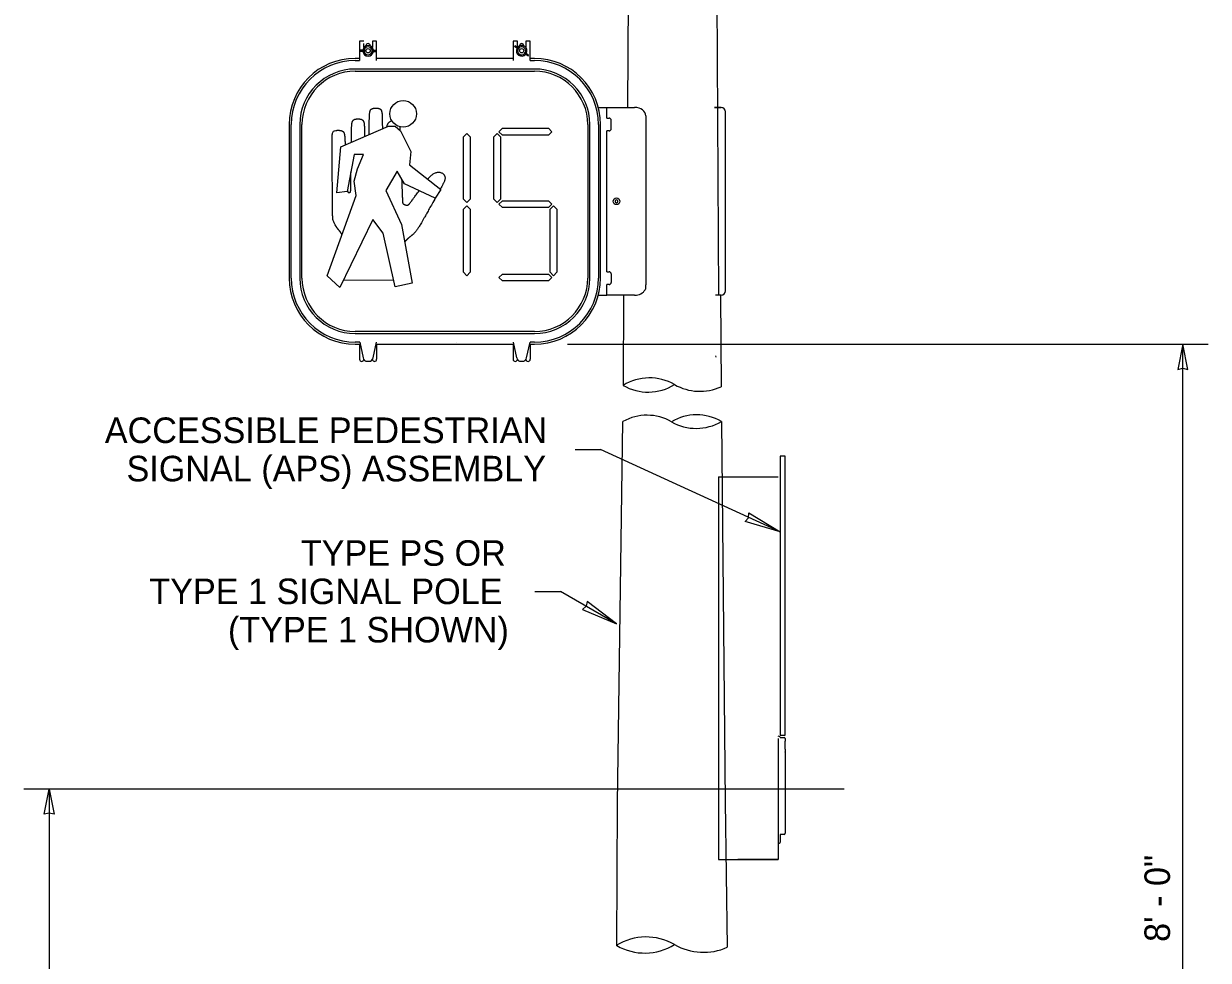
# Model space of a CAD drawing. Extents: x 99862 to 103680, y 99470 to 105076.
# Drawn here: x 101008 to 101750, y 103974 to 104561 of the extents above; entities that cross this region are included whole.
import ezdxf

# ---------------------------------------------------------------- set-up
doc = ezdxf.new("R2010")
doc.units = 0
for name, color, linetype in [('Level 1', 7, 'Continuous'), ('Level 11', 7, 'Continuous'), ('Level 15', 7, 'Continuous'), ('Level 2', 7, 'Continuous'), ('Level 20', 7, 'Continuous'), ('Level 3', 7, 'Continuous'), ('Level 31', 7, 'Continuous'), ('Level 33', 7, 'Continuous'), ('Level 4', 7, 'Continuous'), ('Level 40', 7, 'Continuous'), ('Level 5', 7, 'Continuous'), ('Level 6', 7, 'Continuous'), ('Level 7', 7, 'Continuous'), ('Level 8', 7, 'Continuous')]:
    doc.layers.add(name, color=color, linetype=linetype)

msp = doc.modelspace()

# ---------------------------------------------------------------- linework, layer by layer
at = {"layer": 'Level 1'}
for p, q in [((101218.5, 104359.78), (101218.5, 104353.11)), ((101229.19, 104359.78), (101229.19, 104353.11)), ((101314.69, 104359.78), (101314.69, 104353.11)), ((101325.38, 104359.78), (101325.38, 104353.11)), ((101218.5, 104353.11), (101218.5, 104350.43)), ((101229.19, 104353.11), (101229.19, 104350.43)), ((101314.69, 104353.11), (101314.69, 104350.43)), ((101325.38, 104353.11), (101325.38, 104350.43)), ((101441.95, 104351.66), (101441.62, 104352.51))]:
    msp.add_line(p, q, dxfattribs=at)
for centre, start, end in [((101219.84, 104350.43), 180, 270), ((101219.84, 104350.43), 270, 350.91675), ((101227.86, 104350.43), 189.08325, 270), ((101227.86, 104350.43), 270, 0), ((101316.03, 104350.43), 180, 270), ((101316.03, 104350.43), 270, 350.91675), ((101324.04, 104350.43), 189.08325, 270), ((101324.04, 104350.43), 270, 0)]:
    msp.add_arc(centre, 1.34, start, end, dxfattribs=at)
at = {"layer": 'Level 11'}
msp.add_line((101279.06, 104361.02), (101279.09, 104361.12), dxfattribs=at)
at = {"layer": 'Level 15'}
for p, q in [((101348.74, 104359.78), (101750.13, 104359.78)), ((101734.13, 103694.63), (101734.13, 104359.78)), ((101353.51, 104293.95), (101369.51, 104293.95)), ((101482.04, 104242.25), (101369.51, 104293.95)), ((101328.28, 104205.08), (101344.28, 104205.08)), ((101379.4, 104184.81), (101344.28, 104205.08)), ((101522.08, 104081.21), (101008.13, 104081.21)), ((101024.13, 104081.21), (101024.13, 103694.63))]:
    msp.add_line(p, q, dxfattribs=at)
for points in [[(101734.13, 104359.78), (101731.05, 104344.06), (101734.13, 104344.79), (101737.22, 104344.06)], [(101482.04, 104242.25), (101459.99, 104248.89), (101462.18, 104251.18), (101462.44, 104254.33)], [(101379.4, 104184.81), (101361.12, 104198.81), (101360.54, 104195.7), (101358.13, 104193.64)], [(101024.13, 104081.21), (101027.22, 104065.49), (101024.13, 104066.22), (101021.05, 104065.49)]]:
    msp.add_lwpolyline(points, close=True, dxfattribs=at)
at = {"layer": 'Level 2'}
for p, q in [((101239.95, 104399.78), (101208.3, 104399.89)), ((101251.41, 104398.14), (101240.89, 104395.66))]:
    msp.add_line(p, q, dxfattribs=at)
for points in [[(101240.89, 104395.66), (101233.21, 104429.27), (101226.78, 104437.89), (101206.1, 104395.39), (101198.22, 104402.58), (101216.4, 104452.88), (101215.07, 104461.97), (101217.2, 104469.73), (101220.97, 104478.69), (101215.07, 104478.6), (101210.77, 104455.36), (101204.29, 104454.61), (101206.68, 104483.31), (101236.72, 104496.26), (101240.8, 104496.26), (101244.08, 104493.51), (101250.64, 104480.42), (101249.71, 104472.13), (101269.37, 104456.65), (101265.85, 104451.33), (101246.7, 104460.15), (101241.99, 104468.19), (101234.99, 104456.02), (101244.75, 104434.73), (101251.41, 104398.14)], [(101287.72, 104450.74), (101285.62, 104448.63), (101285.62, 104448.63), (101283.51, 104450.74), (101283.51, 104450.74), (101283.51, 104489.73), (101283.51, 104489.73), (101285.62, 104491.84), (101285.62, 104491.84), (101287.72, 104489.73), (101287.72, 104489.73), (101287.72, 104450.74)], [(101306.88, 104450.74), (101304.77, 104448.63), (101304.77, 104448.63), (101302.66, 104450.74), (101302.66, 104450.74), (101302.66, 104489.73), (101302.66, 104489.73), (101304.77, 104491.84), (101304.77, 104491.84), (101306.88, 104489.73), (101306.88, 104489.73), (101306.88, 104450.74)], [(101336.89, 104495.01), (101339, 104492.9), (101339, 104492.9), (101336.89, 104490.79), (101336.89, 104490.79), (101307.94, 104490.79), (101307.94, 104490.79), (101305.83, 104492.9), (101305.83, 104492.9), (101307.94, 104495.01), (101307.94, 104495.01), (101336.89, 104495.01)], [(101287.72, 104404.83), (101285.62, 104402.72), (101285.62, 104402.72), (101283.51, 104404.83), (101283.51, 104404.83), (101283.51, 104444.41), (101283.51, 104444.41), (101285.62, 104446.52), (101285.62, 104446.52), (101287.72, 104444.41), (101287.72, 104444.41), (101287.72, 104404.83)], [(101336.89, 104449.68), (101339, 104447.57), (101339, 104447.57), (101336.89, 104445.46), (101336.89, 104445.46), (101307.94, 104445.46), (101307.94, 104445.46), (101305.83, 104447.57), (101305.83, 104447.57), (101307.94, 104449.68), (101307.94, 104449.68), (101336.89, 104449.68)], [(101342.17, 104404.83), (101340.06, 104402.72), (101340.06, 104402.72), (101337.95, 104404.83), (101337.95, 104404.83), (101337.95, 104444.41), (101337.95, 104444.41), (101340.06, 104446.52), (101340.06, 104446.52), (101342.17, 104444.41), (101342.17, 104444.41), (101342.17, 104404.83)], [(101336.89, 104403.77), (101339, 104401.66), (101339, 104401.66), (101336.89, 104399.55), (101336.89, 104399.55), (101307.94, 104399.55), (101307.94, 104399.55), (101305.83, 104401.66), (101305.83, 104401.66), (101307.94, 104403.77), (101307.94, 104403.77), (101336.89, 104403.77)]]:
    msp.add_lwpolyline(points, dxfattribs=at)
msp.add_circle((101245.83, 104504.07), 8.35, dxfattribs=at)
for points in [[(101224.47, 104490.98), (101224.57, 104497.33), (101224.68, 104503.68), (101224.68, 104507.69), (101228.69, 104507.69), (101232.7, 104507.69), (101232.7, 104503.68), (101232.75, 104499.12), (101232.8, 104494.57)], [(101213.39, 104486.2), (101213.46, 104491.55), (101213.53, 104496.91), (101213.53, 104500.92), (101217.53, 104500.92), (101221.54, 104500.92), (101221.54, 104496.91), (101221.57, 104493.32), (101221.6, 104489.74)], [(101235.65, 104495.8), (101235.65, 104495.8), (101235.65, 104495.81), (101235.65, 104498.96), (101238.71, 104499.7)], [(101207.54, 104428.36), (101206.72, 104429.88), (101205.59, 104431.2), (101204, 104433.05), (101202.87, 104435.2), (101201.64, 104437.54), (101201.64, 104440.18), (101201.43, 104464.97), (101201.22, 104489.77), (101201.22, 104493.78), (101205.23, 104493.78), (101209.24, 104493.78), (101209.24, 104489.77), (101209.37, 104487.15), (101209.51, 104484.53)], [(101243.66, 104496), (101243.67, 104495.9), (101243.67, 104495.81), (101243.7, 104494.8), (101243.74, 104493.8)], [(101210.97, 104456.42), (101210.98, 104456.12), (101211, 104455.83), (101211, 104454.83), (101212, 104454.83), (101213, 104454.83), (101213, 104455.83), (101213.08, 104462.05), (101213.16, 104468.27)], [(101261.24, 104463.05), (101261.34, 104463.18), (101261.44, 104463.32), (101266.56, 104470.83), (101274.07, 104465.7), (101271.58, 104461.28), (101269.09, 104456.86)], [(101244.88, 104463.26), (101245.14, 104456.28), (101245.4, 104449.31), (101245.4, 104449.39), (101245.39, 104449.47), (101245.4, 104447.6), (101247.2, 104447.07), (101248.99, 104446.55), (101250.01, 104448.12), (101249.9, 104447.98), (101249.79, 104447.83), (101252.83, 104451.88), (101255.88, 104455.92)], [(101266.7, 104452.61), (101261.39, 104443.16), (101256.07, 104433.72), (101253.77, 104429.64), (101249.98, 104426.89), (101248.14, 104425.56), (101246.74, 104423.77)]]:
    msp.add_open_spline(points, degree=4, dxfattribs=at)
at = {"layer": 'Level 3'}
for p, q in [((101221.18, 104549.49), (101218.5, 104549.49)), ((101218.5, 104549.49), (101218.5, 104537.46)), ((101221.18, 104545.54), (101221.18, 104548.15)), ((101226.51, 104549.49), (101226.52, 104545.55)), ((101229.19, 104549.49), (101226.52, 104549.49)), ((101229.19, 104537.46), (101229.19, 104549.49)), ((101317.36, 104549.49), (101314.69, 104549.49)), ((101314.69, 104549.49), (101314.69, 104537.46)), ((101317.36, 104548.15), (101317.36, 104549.49)), ((101317.36, 104545.79), (101317.36, 104548.15)), ((101322.7, 104549.49), (101322.71, 104545.55)), ((101325.38, 104549.49), (101322.71, 104549.49)), ((101325.38, 104537.46), (101325.38, 104549.49)), ((101218.5, 104538.8), (101215.83, 104538.8)), ((101215.83, 104537.46), (101218.5, 104537.46)), ((101314.69, 104538.8), (101229.19, 104538.8)), ((101328.05, 104538.8), (101325.38, 104538.8)), ((101325.38, 104537.46), (101328.05, 104537.46)), ((101328.05, 104532.12), (101215.83, 104532.12)), ((101215.83, 104530.78), (101328.05, 104530.78)), ((101174.42, 104497.39), (101174.42, 104401.2)), ((101175.75, 104401.2), (101175.75, 104497.39)), ((101181.1, 104497.39), (101181.1, 104401.2)), ((101182.43, 104401.2), (101182.43, 104497.39)), ((101361.45, 104497.39), (101361.45, 104401.2)), ((101362.79, 104401.2), (101362.79, 104497.39)), ((101368.13, 104497.39), (101368.13, 104401.2)), ((101369.47, 104401.2), (101369.47, 104497.39)), ((101328.05, 104367.8), (101215.83, 104367.8)), ((101215.83, 104366.46), (101328.05, 104366.46)), ((101218.61, 104361.12), (101215.83, 104361.12)), ((101215.83, 104359.78), (101218.9, 104359.78)), ((101218.61, 104361.12), (101220.73, 104351.21)), ((101226.97, 104351.21), (101229.09, 104361.12)), ((101228.8, 104359.78), (101315.08, 104359.78)), ((101314.8, 104361.12), (101316.91, 104351.21)), ((101323.16, 104351.21), (101325.27, 104361.12)), ((101324.99, 104359.78), (101328.05, 104359.78)), ((101328.05, 104361.12), (101325.27, 104361.12)), ((101223.34, 104349.1), (101224.36, 104349.1)), ((101319.53, 104349.1), (101320.55, 104349.1))]:
    msp.add_line(p, q, dxfattribs=at)
for centre, radius, start, end in [((101215.83, 104497.39), 41.41, 90, 180), ((101215.83, 104497.39), 40.08, 90, 180), ((101328.05, 104497.39), 41.41, 0, 90), ((101328.05, 104497.39), 40.08, 0, 90), ((101215.83, 104497.39), 34.73, 90, 180), ((101215.83, 104497.39), 33.4, 90, 180), ((101328.05, 104497.39), 34.73, 0, 90), ((101328.05, 104497.39), 33.4, 0, 90), ((101215.83, 104401.2), 41.41, 180, 270), ((101215.83, 104401.2), 40.08, 180, 270), ((101215.83, 104401.2), 34.73, 180, 270), ((101215.83, 104401.2), 33.4, 180, 270), ((101328.05, 104401.2), 41.41, 270, 0), ((101328.05, 104401.2), 34.73, 270, 0), ((101328.05, 104401.2), 40.08, 270, 0), ((101328.05, 104401.2), 33.4, 270, 0), ((101223.34, 104351.77), 2.67, 192.04709, 270), ((101224.36, 104351.77), 2.67, 270, 347.95291), ((101319.53, 104351.77), 2.67, 192.04709, 270), ((101320.55, 104351.77), 2.67, 270, 347.95291)]:
    msp.add_arc(centre, radius, start, end, dxfattribs=at)
at = {"layer": 'Level 31'}
for p, q in [((101443.29, 104276.7), (101480.69, 104276.7)), ((101443.29, 104276.7), (101443.29, 104037.17)), ((101480.69, 104112.91), (101480.69, 104047.68)), ((101480.69, 104047.68), (101480.69, 104037.17)), ((101443.29, 104037.17), (101480.69, 104037.17))]:
    msp.add_line(p, q, dxfattribs=at)
at = {"layer": 'Level 33'}
for p, q in [((101481.86, 104113.61), (101484.37, 104113.61)), ((101485.07, 104106.3), (101485.08, 104111.18)), ((101485.08, 104112.91), (101485.08, 104111.18)), ((101485.07, 104106.3), (101485.07, 104053.61)), ((101485.07, 104104.54), (101485.08, 104104.54)), ((101484.37, 104052.91), (101481.86, 104052.91)), ((101481.86, 104052.91), (101481.86, 104048.38)), ((101481.86, 104048.38), (101481.86, 104047.91)), ((101470.91, 104037.17), (101455.38, 104037.17)), ((101480.69, 104037.17), (101470.91, 104037.17))]:
    msp.add_line(p, q, dxfattribs=at)
for centre, radius, start, end in [((101480.69, 104112.91), 1.41, 33.82383, 90), ((101484.37, 104112.91), 0.703, 0, 90), ((101484.37, 104104.54), 0.703, 351.20965, 0), ((101484.37, 104053.61), 0.703, 270, 0), ((101480.69, 104048.69), 1.41, 270, 326.17617)]:
    msp.add_arc(centre, radius, start, end, dxfattribs=at)
msp.add_ellipse((101484.37, 104104.54), major_axis=(0.703, 0), ratio=0.919573, start_param=6.129765, end_param=6.283185, dxfattribs=at)
at = {"layer": 'Level 4'}
for p, q in [((101218.73, 104543.2), (101218.73, 104543.87)), ((101220.35, 104543.87), (101218.73, 104543.87)), ((101220.35, 104543.2), (101218.73, 104543.2)), ((101221.06, 104543.87), (101220.35, 104543.87)), ((101221.06, 104543.2), (101220.35, 104543.2)), ((101221.59, 104543.87), (101221.06, 104543.87)), ((101221.59, 104543.2), (101221.06, 104543.2)), ((101222.51, 104546.74), (101222.51, 104546.6)), ((101225.18, 104546.6), (101225.18, 104546.74)), ((101226.11, 104543.87), (101226.64, 104543.87)), ((101226.11, 104543.2), (101226.64, 104543.2)), ((101226.64, 104543.87), (101227.34, 104543.87)), ((101226.64, 104543.2), (101227.34, 104543.2)), ((101227.34, 104543.87), (101228.96, 104543.87)), ((101227.34, 104543.2), (101228.96, 104543.2)), ((101228.96, 104543.2), (101228.96, 104543.87)), ((101315.64, 104546.17), (101316.02, 104546.72)), ((101316.97, 104545.25), (101315.64, 104546.17)), ((101317.35, 104545.8), (101316.02, 104546.72)), ((101317.55, 104544.85), (101316.97, 104545.25)), ((101317.93, 104545.4), (101317.35, 104545.8)), ((101317.99, 104544.55), (101317.55, 104544.85)), ((101318.36, 104545.1), (101317.93, 104545.4)), ((101318.7, 104546.68), (101318.7, 104546.6)), ((101321.37, 104546.6), (101321.37, 104546.68)), ((101321.71, 104541.98), (101322.14, 104541.68)), ((101322.09, 104542.53), (101322.52, 104542.23)), ((101322.14, 104541.68), (101322.72, 104541.28)), ((101322.52, 104542.23), (101323.1, 104541.83)), ((101322.72, 104541.28), (101324.05, 104540.36)), ((101323.1, 104541.83), (101324.43, 104540.91)), ((101324.05, 104540.36), (101324.43, 104540.91))]:
    msp.add_line(p, q, dxfattribs=at)
for centre in [(101223.85, 104543.54), (101320.04, 104543.54)]:
    msp.add_circle(centre, 1.34, dxfattribs=at)
for centre, radius, start, end in [((101223.85, 104546.74), 1.34, 0, 180), ((101320.04, 104546.68), 1.34, 0, 180), ((101223.85, 104543.54), 3.34, 5.73917, 174.26083), ((101223.85, 104543.54), 3.34, 185.73917, 354.26083), ((101223.85, 104543.54), 2.54, 172.40019, 172.44284), ((101223.85, 104543.54), 2.54, 187.55216, 187.59981), ((101223.85, 104543.54), 2.53, 7.59981, 172.40019), ((101223.85, 104543.54), 2.53, 187.59981, 352.40019), ((101223.85, 104546.74), 1.34, 180, 186.09919), ((101223.85, 104543.54), 2.54, 7.55233, 7.59981), ((101223.85, 104543.54), 2.54, 352.40019, 352.44347), ((101320.04, 104543.54), 3.34, 151.10717, 319.62883), ((101320.04, 104543.54), 3.34, 331.10717, 139.62883), ((101320.04, 104543.54), 2.53, 152.96782, 317.76819), ((101320.04, 104543.54), 2.54, 152.91738, 152.96782), ((101320.04, 104543.54), 2.54, 137.76819, 137.80884), ((101320.04, 104543.54), 2.53, 332.96782, 137.76819), ((101320.04, 104546.68), 1.34, 180, 183.55068), ((101320.04, 104543.54), 2.54, 317.76819, 317.80928), ((101320.04, 104543.54), 2.54, 332.91727, 332.96782)]:
    msp.add_arc(centre, radius, start, end, dxfattribs=at)
for points, degree in [([(101221.59, 104543.87), (101221.51, 104543.87), (101221.43, 104543.87), (101221.35, 104543.87)], 2), ([(101221.59, 104543.2), (101221.51, 104543.2), (101221.43, 104543.2), (101221.35, 104543.2)], 2), ([(101221.59, 104543.87), (101221.56, 104543.69), (101221.56, 104543.5), (101221.57, 104543.31), (101221.58, 104543.28), (101221.58, 104543.24), (101221.59, 104543.2)], 3), ([(101226.11, 104543.87), (101226.19, 104543.87), (101226.27, 104543.87), (101226.35, 104543.87)], 2), ([(101226.11, 104543.87), (101226.14, 104543.69), (101226.14, 104543.5), (101226.12, 104543.31), (101226.12, 104543.28), (101226.12, 104543.24), (101226.11, 104543.2)], 3), ([(101226.11, 104543.2), (101226.19, 104543.2), (101226.27, 104543.2), (101226.35, 104543.2)], 2), ([(101317.99, 104544.55), (101317.92, 104544.59), (101317.85, 104544.64), (101317.79, 104544.69)], 2), ([(101318.36, 104545.1), (101318.24, 104544.96), (101318.13, 104544.81), (101318.04, 104544.64), (101318.02, 104544.61), (101318, 104544.58), (101317.99, 104544.55)], 3), ([(101318.36, 104545.1), (101318.3, 104545.14), (101318.24, 104545.19), (101318.18, 104545.23)], 2), ([(101322.09, 104542.53), (101322, 104542.36), (101321.9, 104542.2), (101321.78, 104542.06), (101321.76, 104542.03), (101321.73, 104542), (101321.71, 104541.98)], 3), ([(101321.71, 104541.98), (101321.77, 104541.93), (101321.84, 104541.89), (101321.91, 104541.84)], 2), ([(101322.09, 104542.53), (101322.15, 104542.48), (101322.22, 104542.44), (101322.29, 104542.39)], 2)]:
    msp.add_open_spline(points, degree=degree, dxfattribs=at)
at = {"layer": 'Level 40'}
msp.add_lwpolyline([(101484.99, 104289.71), (101482.04, 104289.71), (101482.04, 104115.11), (101484.99, 104115.11)], close=True, dxfattribs=at)
at = {"layer": 'Level 5'}
for p, q in [((101373.47, 104508.07), (101379.67, 104508.07)), ((101373.47, 104501.39), (101373.47, 104508.07)), ((101379.67, 104508.07), (101390.82, 104508.07)), ((101440.81, 104507.96), (101444.29, 104507.96)), ((101444.29, 104507.96), (101445.03, 104507.96)), ((101447.72, 104501.29), (101447.72, 104505.29)), ((101373.47, 104501.39), (101374.81, 104501.39)), ((101376.15, 104494.71), (101376.15, 104500.06)), ((101397.83, 104502.73), (101397.83, 104421.56)), ((101447.72, 104397.16), (101447.72, 104501.29)), ((101373.47, 104405.21), (101373.47, 104493.38)), ((101374.81, 104493.38), (101373.47, 104493.38)), ((101373.47, 104405.21), (101374.81, 104405.21)), ((101376.15, 104403.87), (101376.15, 104398.53)), ((101373.47, 104390.51), (101373.47, 104397.19)), ((101374.81, 104397.19), (101373.47, 104397.19)), ((101447.72, 104393.15), (101447.72, 104397.16)), ((101379.67, 104390.51), (101373.47, 104390.51)), ((101390.82, 104390.51), (101379.67, 104390.51)), ((101444.29, 104390.48), (101441.42, 104390.48)), ((101445.03, 104390.48), (101444.29, 104390.48))]:
    msp.add_line(p, q, dxfattribs=at)
for centre, start, end in [((101374.81, 104500.06), 360, 90), ((101374.81, 104494.71), 270, 0), ((101374.81, 104403.87), 360, 90), ((101374.81, 104398.53), 270, 0)]:
    msp.add_arc(centre, 1.34, start, end, dxfattribs=at)
for centre, major_axis, ratio, start_param, end_param in [((101390.82, 104502.73), (-7.02, 0), 0.761681, 3.141593, 4.712389), ((101445.03, 104505.29), (-2.69, 0), 0.992934, 3.141593, 4.712389), ((101390.82, 104395.86), (7.02, 0), 0.761681, 4.712389, 5.904643), ((101445.03, 104393.15), (2.69, 0), 0.992934, 4.712389, 6.283185)]:
    msp.add_ellipse(centre, major_axis=major_axis, ratio=ratio, start_param=start_param, end_param=end_param, dxfattribs=at)
for points, degree in [([(101397.83, 104421.56), (101397.79, 104412.99), (101397.75, 104404.42), (101397.71, 104395.86)], 2), ([(101397.71, 104395.86), (101397.71, 104395.66), (101397.69, 104395.47), (101397.67, 104395.28), (101397.62, 104394.8), (101397.5, 104394.32), (101397.34, 104393.88)], 3)]:
    msp.add_open_spline(points, degree=degree, dxfattribs=at)
at = {"layer": 'Level 6'}
for p, q in [((101368.06, 104508.07), (101373.47, 104508.07)), ((101445.05, 104507.96), (101440.81, 104507.96)), ((101368.06, 104390.51), (101373.47, 104390.51)), ((101445.05, 104390.48), (101441.42, 104390.48))]:
    msp.add_line(p, q, dxfattribs=at)
for centre, start, end in [((101445.05, 104505.29), 0, 90), ((101445.05, 104393.15), 270, 0)]:
    msp.add_arc(centre, 2.67, start, end, dxfattribs=at)
at = {"layer": 'Level 7'}
for p, q in [((101379.49, 104450.29), (101378.62, 104449.79)), ((101378.62, 104449.79), (101378.62, 104448.79)), ((101378.62, 104448.79), (101379.49, 104448.29)), ((101380.35, 104449.79), (101379.49, 104450.29)), ((101379.49, 104448.29), (101380.35, 104448.79)), ((101380.35, 104448.79), (101380.35, 104449.79))]:
    msp.add_line(p, q, dxfattribs=at)
msp.add_ellipse((101379.49, 104449.29), major_axis=(0, 2.09), ratio=0.992746, dxfattribs=at)
at = {"layer": 'Level 8'}
for p, q in [((101386.62, 104507.94), (101386.97, 104576.23)), ((101442.34, 104576.23), (101443.31, 104390.38)), ((101383.73, 104334), (101384.02, 104390.41)), ((101444.64, 104390.51), (101444.94, 104333.19)), ((101380.14, 104072.4), (101383.51, 104311.43)), ((101445.15, 104311.43), (101447.61, 104073.29)), ((101447.61, 104073.29), (101448.85, 103982.24)), ((101379.67, 103983.18), (101380.14, 104072.4))]:
    msp.add_line(p, q, dxfattribs=at)
for centre, radius, start, end in [((101400.11, 104307.36), 31.37, 60, 121.69493), ((101399.32, 104361.21), 31.37, 240, 301.69493), ((101431.67, 104362.44), 32.11, 240.37681, 294.39776), ((101398.54, 104284.71), 30.65, 60, 119.3569), ((101429.69, 104284.53), 31.06, 59.99582, 120.63648), ((101429.36, 104338.08), 30.98, 239.99657, 300.65221), ((101398.02, 103953.12), 35.55, 60, 121.69493), ((101397.12, 104014.16), 35.55, 240.44541, 301.69493), ((101433.96, 104015.46), 36.41, 240.06998, 294.09093)]:
    msp.add_arc(centre, radius, start, end, dxfattribs=at)

# ---------------------------------------------------------------- texts
at = {"layer": 'Level 20'}
for s, p in [('ACCESSIBLE PEDESTRIAN ', (101058.95, 104297.95)), ('SIGNAL (APS) ASSEMBLY ', (101072.54, 104273.95)), ('TYPE PS OR', (101181.71, 104221.08)), ('TYPE 1 SIGNAL POLE', (101086.83, 104197.08)), ('(TYPE 1 SHOWN)', (101136.09, 104173.08))]:
    msp.add_text(s, height=16, dxfattribs=at).set_placement(p)
msp.add_text('8\' - 0"', height=16, rotation=90, dxfattribs=at).set_placement((101726.13, 103985.57))

doc.saveas('drawing.dxf')
